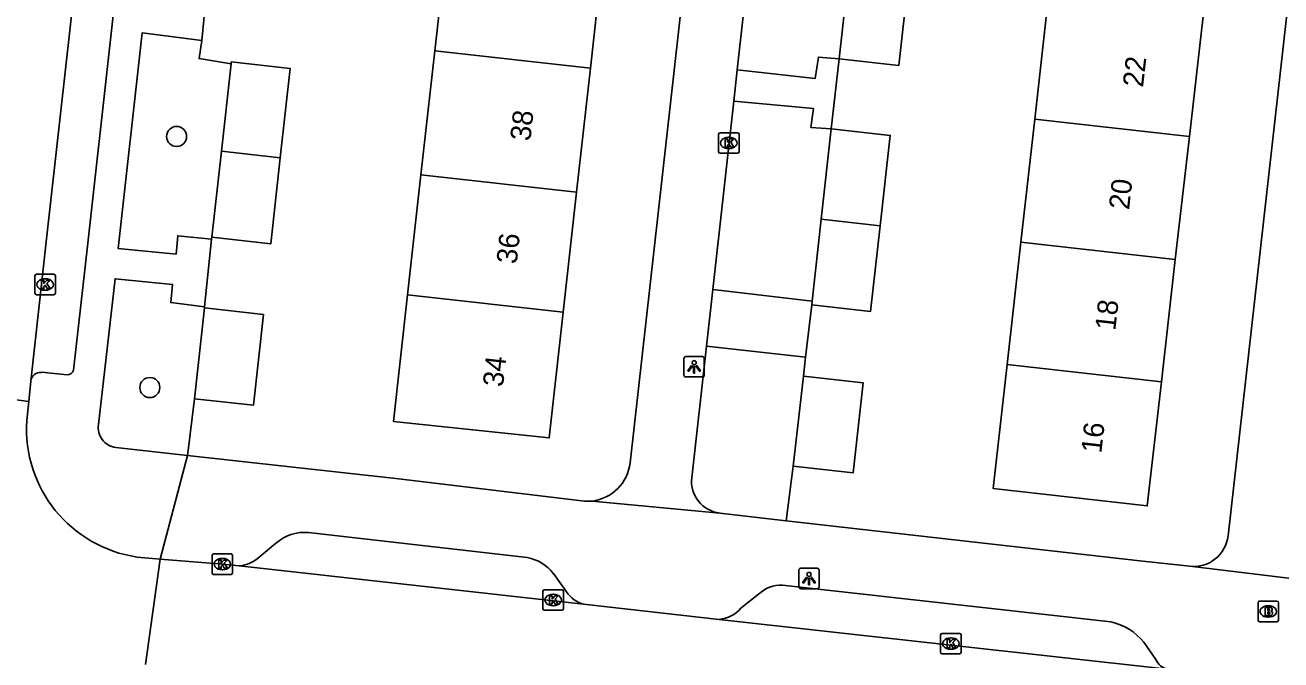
# Model space of a CAD drawing. Extents: x 161928 to 163055, y 386475 to 387428.
# Drawn here: x 162118.7 to 162180.1, y 387155 to 387186 of the extents above; entities that cross this region are included whole.
import ezdxf

# ---------------------------------------------------------------- set-up
doc = ezdxf.new("R2010")
doc.units = 0
for name, color, linetype in [('IMGEO_Boom', 7, 'Continuous'), ('IMGEO_Brandkraan', 7, 'Continuous'), ('IMGEO_Groenvoorziening', 7, 'Continuous'), ('IMGEO_Kolk', 7, 'Continuous'), ('IMGEO_Lichtpunt', 7, 'Continuous'), ('IMGEO_Muur', 7, 'Continuous'), ('IMGEO_Pand', 7, 'Continuous'), ('IMGEO_Pand_nummerreeks', 7, 'Continuous'), ('IMGEO_Rijbaan_lokaal_open', 7, 'Continuous'), ('IMGEO_Voetpad_open', 7, 'Continuous')]:
    doc.layers.add(name, color=color, linetype=linetype)

msp = doc.modelspace()

# ---------------------------------------------------------------- linework, layer by layer
at = {"layer": 'IMGEO_Boom'}
for centre in [(162126.129, 387180.585), (162124.821, 387168.309)]:
    msp.add_circle(centre, 0.489, dxfattribs=at)
at = {"layer": 'IMGEO_Brandkraan'}
for p, q in [((162178.997, 387156.936), (162178.997, 387157.788)), ((162179.072, 387157.862), (162179.924, 387157.862)), ((162179.485, 387157.642), (162179.51, 387157.642)), ((162179.998, 387157.788), (162179.998, 387156.936)), ((162179.508, 387157.082), (162179.483, 387157.082)), ((162179.924, 387156.862), (162179.072, 387156.862))]:
    msp.add_line(p, q, dxfattribs=at)
for points in [[(162178.997, 387156.936), (162178.997, 387157.788)], [(162179.072, 387157.862), (162179.924, 387157.862)], [(162179.345, 387157.562), (162179.345, 387157.162), (162179.558, 387157.162)], [(162179.576, 387157.562), (162179.345, 387157.562)], [(162179.998, 387157.788), (162179.998, 387156.936)], [(162179.524, 387157.481), (162179.47, 387157.481), (162179.47, 387157.405)], [(162179.47, 387157.405), (162179.523, 387157.405)], [(162179.532, 387157.329), (162179.47, 387157.329), (162179.47, 387157.248)], [(162179.47, 387157.248), (162179.532, 387157.248)], [(162179.924, 387156.862), (162179.072, 387156.862)]]:
    msp.add_lwpolyline(points, dxfattribs=at)
for centre, radius, start, end in [((162179.074, 387157.786), 0.0765, 91.55205, 178.44795), ((162179.074, 387157.786), 0.0765, 91.55205, 178.44795), ((162179.58, 387157.417), 0.145, 59.4692, 91.53667), ((162179.605, 387157.464), 0.0922, 285.51372, 58.15012), ((162179.922, 387157.786), 0.0765, 1.55205, 88.44795), ((162179.922, 387157.786), 0.0765, 1.55205, 88.44795), ((162179.074, 387156.938), 0.0765, 181.55205, 268.44795), ((162179.074, 387156.938), 0.0765, 181.55205, 268.44795), ((162179.525, 387157.443), 0.0379, 267.82845, 90.93552), ((162179.533, 387157.288), 0.0404, 269.87594, 90.50774), ((162179.564, 387157.413), 0.251, 268.66757, 293.53466), ((162179.61, 387157.272), 0.105, 301.31148, 78.98903), ((162179.922, 387156.938), 0.0765, 271.55205, 358.44795), ((162179.922, 387156.938), 0.0765, 271.55205, 358.44795)]:
    msp.add_arc(centre, radius, start, end, dxfattribs=at)
for centre, major_axis, ratio, start_param, end_param in [((162179.484, 387157.362), (-0.387, 0.002), 0.722429, 4.712389, 7.853982), ((162179.509, 387157.362), (-0.39, 0.002), 0.717154, 1.570796, 4.712389)]:
    msp.add_ellipse(centre, major_axis=major_axis, ratio=ratio, start_param=start_param, end_param=end_param, dxfattribs=at)
at = {"layer": 'IMGEO_Groenvoorziening'}
for points in [[(162128.795, 387184.141), (162127.225, 387184.39), (162127.362, 387185.278)], [(162127.842, 387175.567), (162127.851, 387175.654)], [(162127.49, 387172.2), (162127.496, 387172.26)], [(162156.878, 387169.796), (162156.769, 387168.871)], [(162126.667, 387164.99), (162126.679, 387165.093), (162126.997, 387167.765)], [(162156.279, 387164.46), (162155.937, 387161.8)]]:
    msp.add_lwpolyline(points, dxfattribs=at)
at = {"layer": 'IMGEO_Kolk'}
for p, q in [((162152.624, 387179.839), (162152.624, 387180.691)), ((162152.699, 387180.765), (162153.551, 387180.765)), ((162153.112, 387180.545), (162153.137, 387180.545)), ((162153.625, 387180.691), (162153.625, 387179.839)), ((162153.551, 387179.765), (162152.699, 387179.765)), ((162153.135, 387179.985), (162153.11, 387179.985)), ((162119.2, 387172.921), (162119.2, 387173.773)), ((162119.275, 387173.847), (162120.127, 387173.847)), ((162119.688, 387173.627), (162119.713, 387173.627)), ((162120.201, 387173.773), (162120.201, 387172.921)), ((162120.127, 387172.847), (162119.275, 387172.847)), ((162119.711, 387173.067), (162119.686, 387173.067)), ((162127.864, 387159.25), (162127.864, 387160.102)), ((162127.939, 387160.176), (162128.791, 387160.176)), ((162128.352, 387159.956), (162128.377, 387159.956)), ((162128.865, 387160.102), (162128.865, 387159.25)), ((162128.375, 387159.396), (162128.35, 387159.396)), ((162128.791, 387159.176), (162127.939, 387159.176)), ((162144.038, 387157.495), (162144.038, 387158.347)), ((162144.113, 387158.421), (162144.965, 387158.421)), ((162144.526, 387158.201), (162144.551, 387158.201)), ((162145.039, 387158.347), (162145.039, 387157.495)), ((162144.549, 387157.641), (162144.524, 387157.641)), ((162144.965, 387157.421), (162144.113, 387157.421)), ((162163.556, 387156.29), (162164.408, 387156.29)), ((162163.481, 387155.364), (162163.481, 387156.216)), ((162163.969, 387156.07), (162163.994, 387156.07)), ((162164.482, 387156.216), (162164.482, 387155.364)), ((162164.408, 387155.29), (162163.556, 387155.29)), ((162163.992, 387155.51), (162163.967, 387155.51))]:
    msp.add_line(p, q, dxfattribs=at)
for points in [[(162152.624, 387179.839), (162152.624, 387180.691)], [(162152.699, 387180.765), (162153.551, 387180.765)], [(162152.945, 387180.465), (162153.068, 387180.465), (162153.068, 387180.314), (162153.198, 387180.465), (162153.362, 387180.465), (162153.216, 387180.314), (162153.369, 387180.065), (162153.217, 387180.065), (162153.132, 387180.229), (162153.068, 387180.162), (162153.068, 387180.065), (162152.945, 387180.065), (162152.945, 387180.465)], [(162153.625, 387180.691), (162153.625, 387179.839)], [(162153.551, 387179.765), (162152.699, 387179.765)], [(162119.2, 387172.921), (162119.2, 387173.773)], [(162119.275, 387173.847), (162120.127, 387173.847)], [(162119.521, 387173.547), (162119.644, 387173.547), (162119.644, 387173.396), (162119.774, 387173.547), (162119.938, 387173.547), (162119.792, 387173.396), (162119.945, 387173.147), (162119.793, 387173.147), (162119.708, 387173.311), (162119.644, 387173.244), (162119.644, 387173.147), (162119.521, 387173.147), (162119.521, 387173.547)], [(162120.201, 387173.773), (162120.201, 387172.921)], [(162120.127, 387172.847), (162119.275, 387172.847)], [(162127.864, 387159.25), (162127.864, 387160.102)], [(162127.939, 387160.176), (162128.791, 387160.176)], [(162128.865, 387160.102), (162128.865, 387159.25)], [(162128.185, 387159.876), (162128.308, 387159.876), (162128.308, 387159.725), (162128.438, 387159.876), (162128.602, 387159.876), (162128.456, 387159.725), (162128.609, 387159.476), (162128.457, 387159.476), (162128.372, 387159.64), (162128.308, 387159.573), (162128.308, 387159.476), (162128.185, 387159.476), (162128.185, 387159.876)], [(162128.791, 387159.176), (162127.939, 387159.176)], [(162144.038, 387157.495), (162144.038, 387158.347)], [(162144.113, 387158.421), (162144.965, 387158.421)], [(162144.359, 387158.121), (162144.482, 387158.121), (162144.482, 387157.97), (162144.612, 387158.121), (162144.776, 387158.121), (162144.63, 387157.97), (162144.783, 387157.721), (162144.631, 387157.721), (162144.546, 387157.885), (162144.482, 387157.818), (162144.482, 387157.721), (162144.359, 387157.721), (162144.359, 387158.121)], [(162145.039, 387158.347), (162145.039, 387157.495)], [(162144.965, 387157.421), (162144.113, 387157.421)], [(162163.556, 387156.29), (162164.408, 387156.29)], [(162163.481, 387155.364), (162163.481, 387156.216)], [(162163.802, 387155.99), (162163.925, 387155.99), (162163.925, 387155.839), (162164.055, 387155.99), (162164.219, 387155.99), (162164.073, 387155.839), (162164.226, 387155.59), (162164.074, 387155.59), (162163.989, 387155.754), (162163.925, 387155.687), (162163.925, 387155.59), (162163.802, 387155.59), (162163.802, 387155.99)], [(162164.482, 387156.216), (162164.482, 387155.364)], [(162164.408, 387155.29), (162163.556, 387155.29)]]:
    msp.add_lwpolyline(points, dxfattribs=at)
for centre, start, end in [((162152.701, 387180.689), 91.55205, 178.44795), ((162152.701, 387180.689), 91.55205, 178.44795), ((162153.549, 387180.689), 1.55205, 88.44795), ((162153.549, 387180.689), 1.55205, 88.44795), ((162152.701, 387179.841), 181.55205, 268.44795), ((162152.701, 387179.841), 181.55205, 268.44795), ((162153.549, 387179.841), 271.55205, 358.44795), ((162153.549, 387179.841), 271.55205, 358.44795), ((162119.277, 387173.771), 91.55205, 178.44795), ((162119.277, 387173.771), 91.55205, 178.44795), ((162120.125, 387173.771), 1.55205, 88.44795), ((162120.125, 387173.771), 1.55205, 88.44795), ((162119.277, 387172.923), 181.55205, 268.44795), ((162119.277, 387172.923), 181.55205, 268.44795), ((162120.125, 387172.923), 271.55205, 358.44795), ((162120.125, 387172.923), 271.55205, 358.44795), ((162127.941, 387160.1), 91.55205, 178.44795), ((162127.941, 387160.1), 91.55205, 178.44795), ((162128.789, 387160.1), 1.55205, 88.44795), ((162128.789, 387160.1), 1.55205, 88.44795), ((162127.941, 387159.252), 181.55205, 268.44795), ((162127.941, 387159.252), 181.55205, 268.44795), ((162128.789, 387159.252), 271.55205, 358.44795), ((162128.789, 387159.252), 271.55205, 358.44795), ((162144.115, 387158.345), 91.55205, 178.44795), ((162144.115, 387158.345), 91.55205, 178.44795), ((162144.963, 387158.345), 1.55205, 88.44795), ((162144.963, 387158.345), 1.55205, 88.44795), ((162144.115, 387157.497), 181.55205, 268.44795), ((162144.115, 387157.497), 181.55205, 268.44795), ((162144.963, 387157.497), 271.55205, 358.44795), ((162144.963, 387157.497), 271.55205, 358.44795), ((162163.558, 387156.214), 91.55205, 178.44795), ((162163.558, 387156.214), 91.55205, 178.44795), ((162164.406, 387156.214), 1.55205, 88.44795), ((162164.406, 387156.214), 1.55205, 88.44795), ((162163.558, 387155.366), 181.55205, 268.44795), ((162163.558, 387155.366), 181.55205, 268.44795), ((162164.406, 387155.366), 271.55205, 358.44795), ((162164.406, 387155.366), 271.55205, 358.44795)]:
    msp.add_arc(centre, 0.0765, start, end, dxfattribs=at)
for centre, major_axis, ratio, start_param, end_param in [((162153.111, 387180.265), (-0.387, 0.002), 0.722429, 4.712389, 7.853982), ((162153.136, 387180.265), (-0.39, 0.002), 0.717154, 1.570796, 4.712389), ((162119.687, 387173.347), (-0.387, 0.002), 0.722429, 4.712389, 7.853982), ((162119.712, 387173.347), (-0.39, 0.002), 0.717154, 1.570796, 4.712389), ((162128.351, 387159.676), (-0.387, 0.002), 0.722429, 4.712389, 7.853982), ((162128.376, 387159.676), (-0.39, 0.002), 0.717154, 1.570796, 4.712389), ((162144.525, 387157.921), (-0.387, 0.002), 0.722429, 4.712389, 7.853982), ((162144.55, 387157.921), (-0.39, 0.002), 0.717154, 1.570796, 4.712389), ((162163.968, 387155.79), (-0.387, 0.002), 0.722429, 4.712389, 7.853982), ((162163.993, 387155.79), (-0.39, 0.002), 0.717154, 1.570796, 4.712389)]:
    msp.add_ellipse(centre, major_axis=major_axis, ratio=ratio, start_param=start_param, end_param=end_param, dxfattribs=at)
at = {"layer": 'IMGEO_Lichtpunt'}
for p, q in [((162151.833, 387169.821), (162151.025, 387169.821)), ((162151.833, 387169.821), (162151.025, 387169.821)), ((162150.931, 387169.726), (162150.931, 387168.919)), ((162150.931, 387169.726), (162150.931, 387168.919)), ((162151.927, 387168.919), (162151.927, 387169.726)), ((162151.927, 387168.919), (162151.927, 387169.726)), ((162151.025, 387168.825), (162151.833, 387168.825)), ((162151.025, 387168.825), (162151.833, 387168.825)), ((162156.546, 387159.376), (162156.546, 387158.569)), ((162156.546, 387159.376), (162156.546, 387158.569)), ((162157.448, 387159.471), (162156.64, 387159.471)), ((162157.448, 387159.471), (162156.64, 387159.471)), ((162157.542, 387158.569), (162157.542, 387159.376)), ((162157.542, 387158.569), (162157.542, 387159.376)), ((162156.64, 387158.475), (162157.448, 387158.475)), ((162156.64, 387158.475), (162157.448, 387158.475))]:
    msp.add_line(p, q, dxfattribs=at)
for points in [[(162151.305, 387169.39), (162151.344, 387169.362), (162151.156, 387169.1), (162151.118, 387169.127), (162151.305, 387169.39)], [(162151.407, 387169.342), (162151.454, 387169.342), (162151.454, 387169.02), (162151.407, 387169.02), (162151.407, 387169.342)], [(162151.517, 387169.362), (162151.555, 387169.389), (162151.742, 387169.127), (162151.703, 387169.099), (162151.517, 387169.362)], [(162156.92, 387159.04), (162156.959, 387159.012), (162156.771, 387158.75), (162156.733, 387158.777), (162156.92, 387159.04)], [(162157.022, 387158.992), (162157.069, 387158.992), (162157.069, 387158.67), (162157.022, 387158.67), (162157.022, 387158.992)], [(162157.132, 387159.012), (162157.17, 387159.039), (162157.357, 387158.777), (162157.318, 387158.749), (162157.132, 387159.012)]]:
    msp.add_lwpolyline(points, dxfattribs=at)
for centre in [(162151.43, 387169.524), (162157.045, 387159.174)]:
    msp.add_circle(centre, 0.0994, dxfattribs=at)
for centre, start, end in [((162151.025, 387169.726), 90, 180), ((162151.025, 387169.726), 90, 180), ((162151.833, 387169.726), 0, 90), ((162151.833, 387169.726), 0, 90), ((162151.025, 387168.919), 180, 270), ((162151.025, 387168.919), 180, 270), ((162151.833, 387168.919), 270, 0), ((162151.833, 387168.919), 270, 360), ((162156.64, 387159.376), 90, 180), ((162156.64, 387159.376), 90, 180), ((162157.448, 387159.376), 0, 90), ((162157.448, 387159.376), 0, 90), ((162156.64, 387158.569), 180, 270), ((162156.64, 387158.569), 180, 270), ((162157.448, 387158.569), 270, 0), ((162157.448, 387158.569), 270, 360)]:
    msp.add_arc(centre, 0.0946, start, end, dxfattribs=at)
at = {"layer": 'IMGEO_Muur'}
msp.add_lwpolyline([(162173.369, 387159.826), (162155.937, 387161.8)], dxfattribs=at)
at = {"layer": 'IMGEO_Pand'}
for points in [[(162139.416, 387190.729), (162138.751, 387184.779)], [(162146.357, 387183.93), (162147.019, 387189.88)], [(162158.516, 387184.381), (162158.973, 387188.489)], [(162161.89, 387188.157), (162161.434, 387184.057), (162158.516, 387184.381)], [(162168.081, 387181.436), (162168.74, 387187.309)], [(162176.309, 387186.46), (162175.64, 387180.588)], [(162138.751, 387184.779), (162138.074, 387178.709)], [(162138.751, 387184.779), (162146.357, 387183.93)], [(162128.319, 387179.86), (162128.795, 387184.141)], [(162131.197, 387179.54), (162131.682, 387183.906), (162128.804, 387184.226), (162128.795, 387184.141)], [(162145.683, 387177.86), (162146.357, 387183.93)], [(162157.645, 387176.546), (162158.135, 387180.955)], [(162158.135, 387180.955), (162161.016, 387180.635), (162160.525, 387176.218)], [(162167.405, 387175.415), (162168.081, 387181.436)], [(162168.081, 387181.436), (162175.64, 387180.588)], [(162175.64, 387180.588), (162174.954, 387174.569)], [(162127.851, 387175.654), (162128.319, 387179.86)], [(162128.319, 387179.86), (162131.197, 387179.54)], [(162127.851, 387175.654), (162130.729, 387175.334), (162131.197, 387179.54)], [(162138.074, 387178.709), (162137.42, 387172.85)], [(162145.683, 387177.86), (162138.074, 387178.709)], [(162145.031, 387172), (162145.683, 387177.86)], [(162157.198, 387172.532), (162157.645, 387176.546)], [(162160.525, 387176.218), (162157.645, 387176.546)], [(162160.525, 387176.218), (162160.059, 387172.03), (162157.178, 387172.35)], [(162166.734, 387169.438), (162167.405, 387175.415)], [(162167.405, 387175.415), (162174.954, 387174.569)], [(162174.954, 387174.569), (162174.273, 387168.593)], [(162137.42, 387172.85), (162136.728, 387166.655), (162144.347, 387165.848), (162145.031, 387172)], [(162137.42, 387172.85), (162145.031, 387172)], [(162157.178, 387172.35), (162157.198, 387172.532)], [(162126.997, 387167.765), (162127.49, 387172.2)], [(162127.49, 387172.2), (162130.376, 387171.879), (162129.883, 387167.444), (162126.997, 387167.765)], [(162174.273, 387168.593), (162173.581, 387162.522), (162166.053, 387163.368), (162166.734, 387169.438)], [(162174.273, 387168.593), (162166.734, 387169.438)], [(162156.769, 387168.871), (162159.693, 387168.546), (162159.203, 387164.135), (162156.279, 387164.46)], [(162156.279, 387164.46), (162156.769, 387168.871)]]:
    msp.add_lwpolyline(points, dxfattribs=at)
at = {"layer": 'IMGEO_Rijbaan_lokaal_open'}
for points in [[(162126.448, 387235.259), (162119.765, 387175.585), (162118.995, 387168.628)], [(162118.995, 387168.628), (162118.898, 387167.619)], [(162118.898, 387167.619), (162113.916, 387168.273)], [(162118.898, 387167.619), (162118.805, 387166.694)], [(162124.201, 387160.022), (162125.322, 387159.911)], [(162125.322, 387159.911), (162124.603, 387154.771)], [(162129.193, 387159.584), (162128.365, 387159.676), (162125.322, 387159.911)], [(162146.17, 387157.696), (162129.193, 387159.584)], [(162152.651, 387156.975), (162146.17, 387157.696)], [(162174.573, 387154.541), (162152.651, 387156.975)]]:
    msp.add_lwpolyline(points, dxfattribs=at)
msp.add_arc((162125.116, 387166.28), 6.324, 176.2439, 261.6847, dxfattribs=at)
at = {"layer": 'IMGEO_Voetpad_open'}
for points in [[(162128.339, 387234.25), (162121.784, 387175.371), (162121.082, 387169.158)], [(162155.986, 387233.092), (162148.298, 387164.623)], [(162184.099, 387219.432), (162177.534, 387161.061)], [(162153.535, 387183.837), (162154.692, 387194.21)], [(162127.362, 387185.278), (162127.511, 387186.795)], [(162127.362, 387185.278), (162124.45, 387185.658), (162123.274, 387175.103), (162126.102, 387174.838), (162126.186, 387175.732), (162127.842, 387175.567)], [(162153.535, 387183.837), (162157.347, 387183.411), (162157.507, 387184.464), (162158.516, 387184.381)], [(162158.516, 387184.381), (162158.135, 387180.955)], [(162153.365, 387182.31), (162153.535, 387183.837)], [(162152.338, 387173.103), (162153.365, 387182.31)], [(162158.135, 387180.955), (162157.138, 387181.026), (162157.272, 387181.952), (162153.365, 387182.31)], [(162127.496, 387172.26), (162127.842, 387175.567)], [(162122.312, 387166.503), (162123.12, 387173.627), (162125.935, 387173.348), (162125.84, 387172.46), (162127.496, 387172.26)], [(162152.028, 387170.329), (162152.338, 387173.103)], [(162157.198, 387172.532), (162152.338, 387173.103)], [(162156.878, 387169.796), (162157.178, 387172.35)], [(162151.311, 387163.901), (162152.028, 387170.329)], [(162152.028, 387170.329), (162156.878, 387169.796)], [(162120.771, 387168.932), (162119.521, 387169.053)], [(162126.667, 387164.99), (162123.153, 387165.379)], [(162125.322, 387159.911), (162126.667, 387164.99)], [(162145.944, 387162.762), (162136.852, 387163.862), (162126.667, 387164.99)], [(162146.449, 387162.761), (162152.694, 387162.167)], [(162152.694, 387162.167), (162155.937, 387161.8)], [(162155.937, 387161.8), (162173.369, 387159.826), (162175.662, 387159.569)], [(162132.583, 387161.221), (162143.272, 387159.996)], [(162130.169, 387160.016), (162130.97, 387160.676)], [(162175.662, 387159.569), (162182.239, 387158.771)], [(162144.554, 387159.209), (162145.277, 387158.205)], [(162153.719, 387157.528), (162154.583, 387158.2)], [(162155.752, 387158.644), (162171.799, 387156.858)], [(162173.41, 387155.854), (162174.006, 387155.016)]]:
    msp.add_lwpolyline(points, dxfattribs=at)
for centre, radius, start, end in [((162119.481, 387168.564), 0.49, 85.34333, 172.53204), ((162120.788, 387169.236), 0.304, 266.8065, 345.20442), ((162123.269, 387166.342), 0.97, 170.46849, 263.1407), ((162146.198, 387164.86), 2.114, 276.83077, 353.57065), ((162152.872, 387163.727), 1.57, 173.64165, 263.50853), ((162146.201, 387164.953), 2.206, 263.31281, 276.46027), ((162132.392, 387159.126), 2.104, 84.79957, 132.53856), ((162175.852, 387161.25), 1.692, 263.53639, 353.5739), ((162128.986, 387161.37), 1.798, 276.60918, 311.14138), ((162142.914, 387157.975), 2.052, 36.9572, 79.95255), ((162146.371, 387159.086), 1.404, 218.84859, 261.7861), ((162155.672, 387157.094), 1.552, 87.04344, 134.55129), ((162152.545, 387158.488), 1.516, 274.01053, 320.73883), ((162171.213, 387154.123), 2.797, 38.23367, 77.90274), ((162174.747, 387155.325), 0.803, 202.63256, 257.45876)]:
    msp.add_arc(centre, radius, start, end, dxfattribs=at)

# ---------------------------------------------------------------- texts
at = {"layer": 'IMGEO_Pand_nummerreeks'}
for s, rotation, p in [('22', 83.49934, (162173.374, 387182.962)), ('38', 83.65553, (162143.421, 387180.334)), ('20', 83.49934, (162172.692, 387176.974)), ('36', 83.65553, (162142.753, 387174.321)), ('18', 83.49934, (162172.019, 387171.07)), ('34', 83.65553, (162142.085, 387168.311)), ('16', 83.49934, (162171.336, 387165.073))]:
    msp.add_text(s, height=1, rotation=rotation, dxfattribs=at).set_placement(p)

doc.saveas('drawing.dxf')
